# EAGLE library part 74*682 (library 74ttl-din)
8-bit MAGNITUDE/IDENTITY COMPARATOR, totem pole
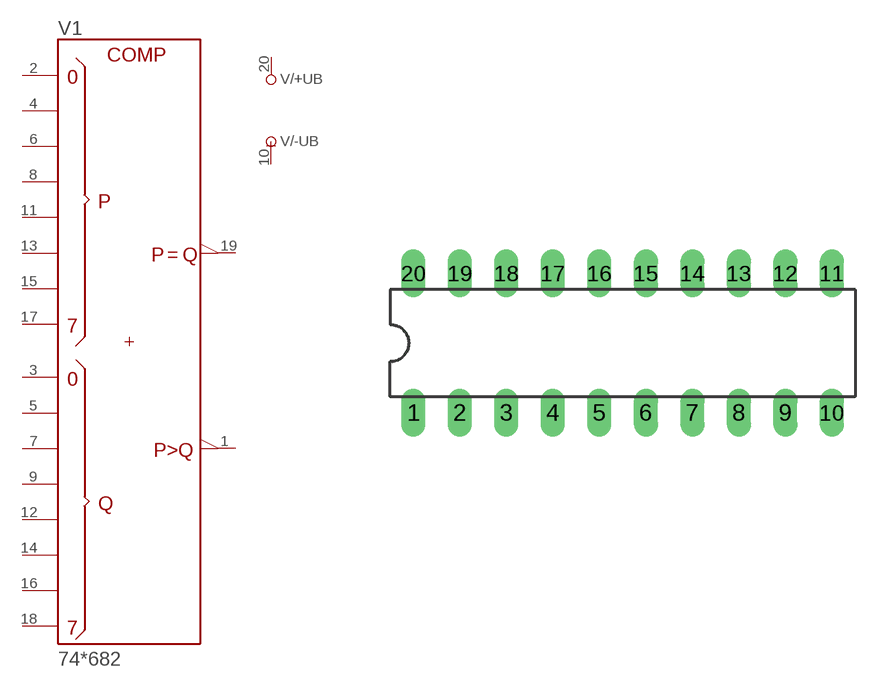
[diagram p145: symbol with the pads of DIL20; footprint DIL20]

Designator prefix V; gates /+UB=+UB /-UB=-UB 1=682

## 74682N  [DIL20]
1  1:P>Q\  out
2  1:P0  in
3  1:Q0  in
4  1:P1  in
5  1:Q1  in
6  1:P2  in
7  1:Q2  in
8  1:P3  in
9  1:Q3  in
10  /-UB:-UB  pwr
11  1:P4  in
12  1:Q4  in
13  1:P5  in
14  1:Q5  in
15  1:P6  in
16  1:Q6  in
17  1:P7  in
18  1:Q7  in
19  1:P=Q\  out
20  /+UB:+UB  pwr

## Footprint DIL20 (pad centres in mm)
Dual In Line Package
drill 0.813 long: 1 -11.43,-3.81; 2 -8.89,-3.81; 3 -6.35,-3.81; 4 -3.81,-3.81; 5 -1.27,-3.81; 6 1.27,-3.81; 7 3.81,-3.81; 8 6.35,-3.81; 9 8.89,-3.81; 10 11.43,-3.81; 11 11.43,3.81; 12 8.89,3.81; 13 6.35,3.81; 14 3.81,3.81; 15 1.27,3.81; 16 -1.27,3.81; 17 -3.81,3.81; 18 -6.35,3.81; 19 -8.89,3.81; 20 -11.43,3.81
